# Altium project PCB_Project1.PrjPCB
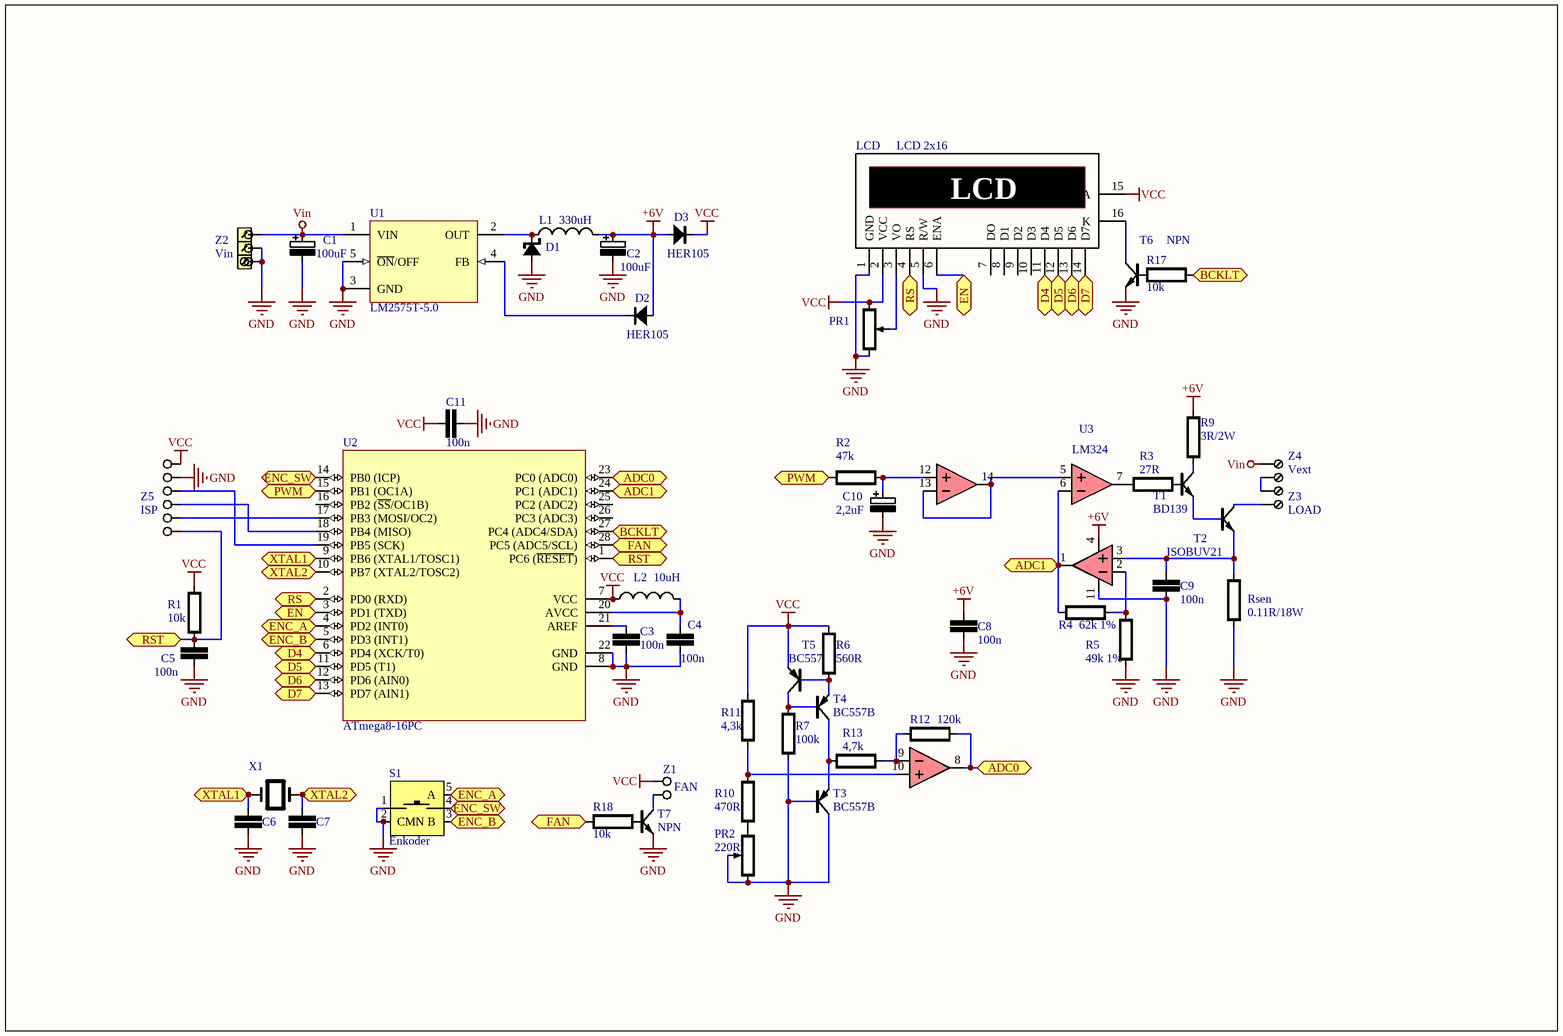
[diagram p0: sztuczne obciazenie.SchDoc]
1 sheet, 51 parts. Net scope: flat (ports and power ports of the same name join across sheets).
Board file: sztuczne obciazenie_2.PcbDoc

## Sheet sztuczne obciazenie.SchDoc
size A4

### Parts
C1  100uF  [CE6]
C2  100uF  [CE7]
C3  100n  [C2]
C4  100n  [C2]
C5  100n  [C2]
C6  C  [C2]  (value not drawn)
C7  C  [C2]  (value not drawn)
C8  100n  [C2]
C9  100n  [C2]
C10  2,2uF  [CE6]
C11  100n  [C2]
D1  (no value)  [D3]
D2  HER105  [D3]
D3  HER105  [D2]
L1  330uH  [CE7]
L2  value 10uH  [R3]
LCD  LCD 2x16  [LCD16*2_B]
PR1  (no value)  [PR]
PR2  value 220R  [PR7]  (hidden comment: POT)
R1  10k  [R3]
R2  47k  [R3]
R3  27R  [R3]
R4  62k 1%  [R3]
R5  49k 1%  [R3]
R6  value 560R  [R3]  (hidden comment: R)
R7  value 100k  [R3]  (hidden comment: R)
R9  3R/2W  [R3]
R10  value 470R  [R3]
R11  value 4,3k  [R3]
R12  value 120k  [R3]
R13  value 4,7k  [R3]
R17  10k  [R3]
R18  10k  [R3]
Rsen  0.11R/18W  [R4]
S1  Enkoder  [HDR2X3]
T1  BD139  [BD1]
T2  ISOBUV21  [TUNIW]
T3  BC557B  [T_1]
T4  BC557B  [T_1]
T5  BC557B  [T_1]
T6  NPN  [T_1]
T7  NPN  [T_1]
U1  LM2575T-5.0  [T05A]
U2  ATmega8-16PC  [U28_mala]
U3  (no value)  (parts A,B,C,D of 4)
X1  (no value)  [X]
Z1  FAN  [JMP2]
Z2  Vin  [ARK3]
Z3  LOAD  [ARK2]
Z4  Vext  [ARK2]
Z5  ISP  [GOLDPIN 6]

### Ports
ADC0 (bidir), ADC1 (bidir), BCKLT (bidir), D4 (bidir), D5 (bidir), D6 (bidir), D7 (bidir), EN (bidir), ENC_A (bidir), ENC_B (bidir), ENC_SW (bidir), FAN (bidir), PWM (bidir), RS (bidir), RST (bidir), XTAL1 (bidir), XTAL2 (bidir)

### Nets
+6V: C2.1 C8.2 D2.1(A) D3.1(A) L1.2 R9.2(BOT) U3.4
GND: C1.2 C2.2 C3.2 C4.2 C5.2 C6.1 C7.2 C8.1 C9.1 C10.2 C11.1 D1.1(A) LCD.1(GND) LCD.5(R/W) PR1.1 PR2.2(TAP) PR2.3(BOT) R5.1(TOP) R7.2(BOT) Rsen.1(TOP) S1.1 S1.2(CMN) T3.2(B) T3.3(C) T6.1(C) T7.1(C) U1.3(GND) U1.5(~{ON}/OFF) U2.8(GND) U2.22(GND) U3.11 Z2.2 Z2.3 Z5.2
VCC: C11.2 D3.2(K) L2.1 LCD.2(VCC) LCD.15(A) PR1.3 R1.2(BOT) R6.1(TOP) R11.2(BOT) T5.1(E) U2.7(VCC) Z1.1 Z5.1
Vin: C1.1 U1.1(VIN) Z2.1 Z4.2
NetC3_1: C3.1 U2.21(AREF)
NetC4_1: C4.1 L2.2 U2.20(AVCC)
NetC5_1: C5.1 R1.1(TOP) U2.1(PC6_(~{RESET})) Z5.6 ; port RST
NetC6_2: C6.2 U2.9(PB6_(XTAL1/TOSC1)) X1.2 ; port XTAL1
NetC7_1: C7.1 U2.10(PB7_(XTAL2/TOSC2)) X1.1 ; port XTAL2
NetC9_2: C9.2 Rsen.2(BOT) T2.1(E) U3.3
NetC10_1: C10.1 R2.2(BOT) U3.12
NetD1_2: D1.2(K) L1.1 U1.2(OUT)
NetD2_2: D2.2(K) U1.4(FB)
NetLCD_3: LCD.3(VO) PR1.2
NetLCD_4: LCD.4(RS) U2.2(PD0_(RXD)) ; port RS
NetLCD_6: LCD.6(ENA) U2.3(PD1_(TXD)) ; port EN
NetLCD_11: LCD.11(D4) U2.6(PD4_(XCK/T0)) ; port D4
NetLCD_12: LCD.12(D5) U2.11(PD5_(T1)) ; port D5
NetLCD_13: LCD.13(D6) U2.12(PD6_(AIN0)) ; port D6
NetLCD_14: LCD.14(D7) U2.13(PD7_(AIN1)) ; port D7
NetLCD_16: LCD.16(K) T6.3(E)
NetPR2_1: PR2.1(TOP) R10.1(TOP)
NetR2_1: R2.1(TOP) U2.15(PB1_(OC1A)) ; port PWM
NetR3_1: R3.1(TOP) U3.7
NetR3_2: R3.2(BOT) T1.2(B)
NetR4_1: R4.1(TOP) U2.24(PC1_(ADC1)) U3.1 U3.6 ; port ADC1
NetR4_2: R4.2(BOT) R5.2(BOT) U3.2
NetR6_2: R6.2(BOT) T4.1(E) T5.2(B)
NetR7_1: R7.1(TOP) T4.2(B) T5.3(C)
NetR9_1: R9.1(TOP) T1.3(C)
NetR10_2: R10.2(BOT) R11.1(TOP) U3.10
NetR12_1: R12.1(TOP) U2.23(PC0_(ADC0)) U3.8 ; port ADC0
NetR12_2: R12.2(BOT) R13.1(TOP) U3.9
NetR13_2: R13.2(BOT) T3.1(E) T4.3(C)
NetR17_1: R17.1(TOP) U2.27(PC4_(ADC4/SDA)) ; port BCKLT
NetR17_2: R17.2(BOT) T6.2(B)
NetR18_1: R18.1(TOP) T7.2(B)
NetR18_2: R18.2(BOT) U2.28(PC5_(ADC5/SCL)) ; port FAN
NetS1_3: S1.3(B) U2.5(PD3_(INT1)) ; port ENC_B
NetS1_4: S1.4 U2.14(PB0_(ICP)) ; port ENC_SW
NetS1_5: S1.5(A) U2.4(PD2_(INT0)) ; port ENC_A
NetT1_1: T1.1(E) T2.2(B)
NetT2_3: T2.3(C) Z3.1
NetT7_3: T7.3(E) Z1.2
NetU2_17: U2.17(PB3_(MOSI/OC2)) Z5.5
NetU2_18: U2.18(PB4_(MISO)) Z5.4
NetU2_19: U2.19(PB5_(SCK)) Z5.3
NetU3_5: U3.5 U3.13 U3.14
NetZ3_2: Z3.2 Z4.1

Not connected (* = marked no-connect by the designer): LCD 7(DO) 8(D1) 9(D2) 10(D3); U2 16(PB2_(~{SS}/OC1B)) 25(PC2_(ADC2)) 26(PC3_(ADC3))

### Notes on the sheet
- U3
- (near U3) LM324

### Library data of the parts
C1 C2 C10 = EL: Elektrolit
C3-C9 C11 = C: Kondensator
D1 = D SCHOTTKY: Dioda Schottky
D2 D3 = D: Dioda
L1 L2 = L2: Cewka
LCD = LCD
PR1 PR2 = POT: Potencjometr
R1-R7 R9-R13 R17 R18 Rsen = R: Rezystor
T1 T2 T6 T7 = NPN: Tranzystor NPN
T3-T5 = PNP: Tranzystor PNP
U1 = LM2575T-5.0: SIMPLE SWITCHER® 1A Step-Down Voltage Regulator, 5-pin TO-220; Manufacturer: National Semiconductor; PackageTopMarking: NSUZXYTTE#*LM2575T*-5.0 P+; PowerWise: N
U2 = ATmega8-16PC: 8-Bit AVR Microcontroller with 8K Bytes of In-System Programmable Flash Memory
U3 = LM324
X1 = X
Z1 = JMP2
Z2 = ARK 3
Z3 Z4 = ARK2
Z5 = GOLDPINX6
